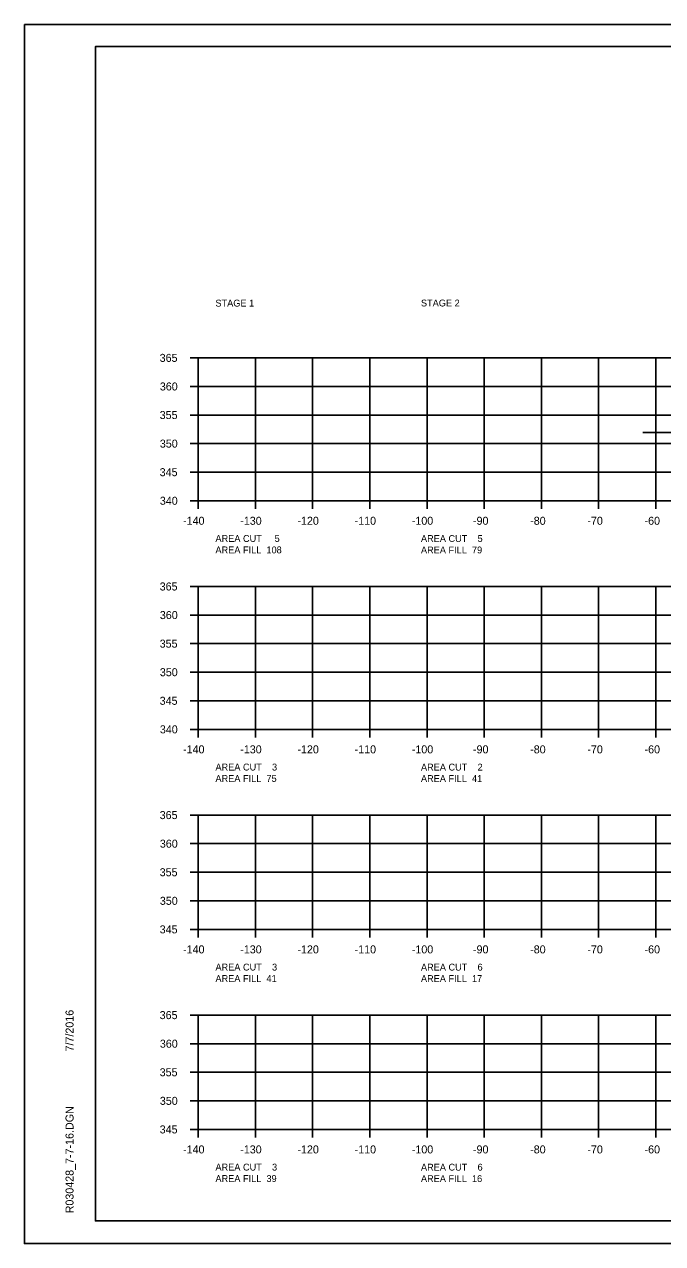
# Model space of a CAD drawing. Extents: x 1374859 to 1376773, y 382242 to 389804.
# Drawn here: x 1375964.2 to 1376075.8, y 382241.7 to 382455.1 of the extents above; entities that cross this region are included whole.
import ezdxf

# ---------------------------------------------------------------- set-up
doc = ezdxf.new("R2010")
doc.units = 0
for name, color, linetype in [('R_Axis', 7, 'Continuous'), ('R_Axis Annot', 7, 'Continuous'), ('R_Border', 7, 'Continuous'), ('R_Exist Surface', 7, 'Continuous'), ('R_Grid', 7, 'Continuous'), ('R_No Plot', 7, 'Continuous')]:
    doc.layers.add(name, color=color, linetype=linetype)

msp = doc.modelspace()

# ---------------------------------------------------------------- linework, layer by layer
at = {"layer": 'R_Axis'}
for p, q in [((1375993.17, 382396.72), (1375994.57, 382396.72)), ((1375994.57, 382371.72), (1375994.57, 382396.72)), ((1375993.17, 382391.72), (1375994.57, 382391.72)), ((1375993.17, 382386.72), (1375994.57, 382386.72)), ((1375993.17, 382381.72), (1375994.57, 382381.72)), ((1375993.17, 382376.72), (1375994.57, 382376.72)), ((1375993.17, 382371.72), (1375994.57, 382371.72)), ((1375994.57, 382371.72), (1376274.57, 382371.72)), ((1375994.57, 382370.32), (1375994.57, 382371.72)), ((1376004.57, 382370.32), (1376004.57, 382371.72)), ((1376014.57, 382370.32), (1376014.57, 382371.72)), ((1376024.57, 382370.32), (1376024.57, 382371.72)), ((1376034.57, 382370.32), (1376034.57, 382371.72)), ((1376044.57, 382370.32), (1376044.57, 382371.72)), ((1376054.57, 382370.32), (1376054.57, 382371.72)), ((1376064.57, 382370.32), (1376064.57, 382371.72)), ((1376074.57, 382370.32), (1376074.57, 382371.72)), ((1375993.17, 382356.72), (1375994.57, 382356.72)), ((1375994.57, 382331.72), (1375994.57, 382356.72)), ((1375993.17, 382351.72), (1375994.57, 382351.72)), ((1375993.17, 382346.72), (1375994.57, 382346.72)), ((1375993.17, 382341.72), (1375994.57, 382341.72)), ((1375993.17, 382336.72), (1375994.57, 382336.72)), ((1375993.17, 382331.72), (1375994.57, 382331.72)), ((1375994.57, 382331.72), (1376274.57, 382331.72)), ((1375994.57, 382330.32), (1375994.57, 382331.72)), ((1376004.57, 382330.32), (1376004.57, 382331.72)), ((1376014.57, 382330.32), (1376014.57, 382331.72)), ((1376024.57, 382330.32), (1376024.57, 382331.72)), ((1376034.57, 382330.32), (1376034.57, 382331.72)), ((1376044.57, 382330.32), (1376044.57, 382331.72)), ((1376054.57, 382330.32), (1376054.57, 382331.72)), ((1376064.57, 382330.32), (1376064.57, 382331.72)), ((1376074.57, 382330.32), (1376074.57, 382331.72)), ((1375993.17, 382316.72), (1375994.57, 382316.72)), ((1375994.57, 382296.72), (1375994.57, 382316.72)), ((1375993.17, 382311.72), (1375994.57, 382311.72)), ((1375993.17, 382306.72), (1375994.57, 382306.72)), ((1375993.17, 382301.72), (1375994.57, 382301.72)), ((1375993.17, 382296.72), (1375994.57, 382296.72)), ((1375994.57, 382296.72), (1376274.57, 382296.72)), ((1375994.57, 382295.32), (1375994.57, 382296.72)), ((1376004.57, 382295.32), (1376004.57, 382296.72)), ((1376014.57, 382295.32), (1376014.57, 382296.72)), ((1376024.57, 382295.32), (1376024.57, 382296.72)), ((1376034.57, 382295.32), (1376034.57, 382296.72)), ((1376044.57, 382295.32), (1376044.57, 382296.72)), ((1376054.57, 382295.32), (1376054.57, 382296.72)), ((1376064.57, 382295.32), (1376064.57, 382296.72)), ((1376074.57, 382295.32), (1376074.57, 382296.72)), ((1375993.17, 382281.72), (1375994.57, 382281.72)), ((1375994.57, 382261.72), (1375994.57, 382281.72)), ((1375993.17, 382276.72), (1375994.57, 382276.72)), ((1375993.17, 382271.72), (1375994.57, 382271.72)), ((1375993.17, 382266.72), (1375994.57, 382266.72)), ((1375993.17, 382261.72), (1375994.57, 382261.72)), ((1375994.57, 382261.72), (1376274.57, 382261.72)), ((1375994.57, 382260.32), (1375994.57, 382261.72)), ((1376004.57, 382260.32), (1376004.57, 382261.72)), ((1376014.57, 382260.32), (1376014.57, 382261.72)), ((1376024.57, 382260.32), (1376024.57, 382261.72)), ((1376034.57, 382260.32), (1376034.57, 382261.72)), ((1376044.57, 382260.32), (1376044.57, 382261.72)), ((1376054.57, 382260.32), (1376054.57, 382261.72)), ((1376064.57, 382260.32), (1376064.57, 382261.72)), ((1376074.57, 382260.32), (1376074.57, 382261.72))]:
    msp.add_line(p, q, dxfattribs=at)
at = {"layer": 'R_Border'}
for p, q in [((1375976.57, 382451.18), (1376292.75, 382451.18)), ((1375976.57, 382245.72), (1375976.57, 382451.18)), ((1375976.57, 382245.72), (1375976.57, 382245.72)), ((1376292.75, 382245.72), (1375976.57, 382245.72))]:
    msp.add_line(p, q, dxfattribs=at)
at = {"layer": 'R_Exist Surface'}
msp.add_lwpolyline([(1376072.31, 382383.65), (1376074.07, 382383.65), (1376082.2, 382383.68)], dxfattribs=at)
at = {"layer": 'R_Grid'}
for p, q in [((1375994.57, 382396.72), (1376274.57, 382396.72)), ((1375994.57, 382371.72), (1375994.57, 382396.72)), ((1376004.57, 382371.72), (1376004.57, 382396.72)), ((1376014.57, 382371.72), (1376014.57, 382396.72)), ((1376024.57, 382371.72), (1376024.57, 382396.72)), ((1376034.57, 382371.72), (1376034.57, 382396.72)), ((1376044.57, 382371.72), (1376044.57, 382396.72)), ((1376054.57, 382371.72), (1376054.57, 382396.72)), ((1376064.57, 382371.72), (1376064.57, 382396.72)), ((1376074.57, 382371.72), (1376074.57, 382396.72)), ((1375994.57, 382391.72), (1376274.57, 382391.72)), ((1375994.57, 382386.72), (1376274.57, 382386.72)), ((1375994.57, 382381.72), (1376274.57, 382381.72)), ((1375994.57, 382376.72), (1376274.57, 382376.72)), ((1375994.57, 382371.72), (1376274.57, 382371.72)), ((1375994.57, 382356.72), (1376274.57, 382356.72)), ((1375994.57, 382331.72), (1375994.57, 382356.72)), ((1376004.57, 382331.72), (1376004.57, 382356.72)), ((1376014.57, 382331.72), (1376014.57, 382356.72)), ((1376024.57, 382331.72), (1376024.57, 382356.72)), ((1376034.57, 382331.72), (1376034.57, 382356.72)), ((1376044.57, 382331.72), (1376044.57, 382356.72)), ((1376054.57, 382331.72), (1376054.57, 382356.72)), ((1376064.57, 382331.72), (1376064.57, 382356.72)), ((1376074.57, 382331.72), (1376074.57, 382356.72)), ((1375994.57, 382351.72), (1376274.57, 382351.72)), ((1375994.57, 382346.72), (1376274.57, 382346.72)), ((1375994.57, 382341.72), (1376274.57, 382341.72)), ((1375994.57, 382336.72), (1376274.57, 382336.72)), ((1375994.57, 382331.72), (1376274.57, 382331.72)), ((1375994.57, 382316.72), (1376274.57, 382316.72)), ((1375994.57, 382296.72), (1375994.57, 382316.72)), ((1376004.57, 382296.72), (1376004.57, 382316.72)), ((1376014.57, 382296.72), (1376014.57, 382316.72)), ((1376024.57, 382296.72), (1376024.57, 382316.72)), ((1376034.57, 382296.72), (1376034.57, 382316.72)), ((1376044.57, 382296.72), (1376044.57, 382316.72)), ((1376054.57, 382296.72), (1376054.57, 382316.72)), ((1376064.57, 382296.72), (1376064.57, 382316.72)), ((1376074.57, 382296.72), (1376074.57, 382316.72)), ((1375994.57, 382311.72), (1376274.57, 382311.72)), ((1375994.57, 382306.72), (1376274.57, 382306.72)), ((1375994.57, 382301.72), (1376274.57, 382301.72)), ((1375994.57, 382296.72), (1376274.57, 382296.72)), ((1375994.57, 382281.72), (1376274.57, 382281.72)), ((1375994.57, 382261.72), (1375994.57, 382281.72)), ((1376004.57, 382261.72), (1376004.57, 382281.72)), ((1376014.57, 382261.72), (1376014.57, 382281.72)), ((1376024.57, 382261.72), (1376024.57, 382281.72)), ((1376034.57, 382261.72), (1376034.57, 382281.72)), ((1376044.57, 382261.72), (1376044.57, 382281.72)), ((1376054.57, 382261.72), (1376054.57, 382281.72)), ((1376064.57, 382261.72), (1376064.57, 382281.72)), ((1376074.57, 382261.72), (1376074.57, 382281.72)), ((1375994.57, 382276.72), (1376274.57, 382276.72)), ((1375994.57, 382271.72), (1376274.57, 382271.72)), ((1375994.57, 382266.72), (1376274.57, 382266.72)), ((1375994.57, 382261.72), (1376274.57, 382261.72))]:
    msp.add_line(p, q, dxfattribs=at)
at = {"layer": 'R_No Plot'}
for p, q in [((1375964.17, 382455.07), (1376297.5, 382455.07)), ((1375964.17, 382241.74), (1376297.5, 382241.74))]:
    msp.add_line(p, q, dxfattribs=at)
for points in [[(1375964.16, 382455.07), (1376297.5, 382455.07), (1376297.5, 382241.74), (1375964.16, 382241.74)], [(1376210.49, 382451.18), (1376210.49, 382441.3), (1376246.22, 382441.3), (1376246.22, 382438.38), (1376269.42, 382438.38), (1376269.42, 382414.05), (1376292.75, 382414.05), (1376292.75, 382245.72), (1375976.57, 382245.72), (1375976.57, 382451.18)]]:
    msp.add_lwpolyline(points, close=True, dxfattribs=at)

# ---------------------------------------------------------------- texts
at = {"layer": 'R_Axis Annot'}
for s, p in [('STAGE 1', (1375997.57, 382405.7)), ('STAGE 2', (1376033.51, 382405.72))]:
    msp.add_text(s, height=1.2, rotation=360, dxfattribs=at).set_placement(p)
for s, height, p in [('365', 1.4, (1375987.82, 382396.02)), ('360', 1.4, (1375987.85, 382391.02)), ('355', 1.4, (1375987.82, 382386.02)), ('350', 1.4, (1375987.85, 382381.02)), ('345', 1.4, (1375987.82, 382376.02)), ('340', 1.4, (1375987.85, 382371.02)), ('-140', 1.4, (1375991.91, 382367.52)), ('-130', 1.4, (1376001.91, 382367.52)), ('-120', 1.4, (1376011.91, 382367.52)), ('-110', 1.4, (1376021.91, 382367.52)), ('-100', 1.4, (1376031.91, 382367.52)), ('-90', 1.4, (1376042.61, 382367.52)), ('-80', 1.4, (1376052.61, 382367.52)), ('-70', 1.4, (1376062.61, 382367.52)), ('-60', 1.4, (1376072.61, 382367.52)), ('AREA CUT     5', 1.2, (1375997.57, 382364.52)), ('AREA CUT    5', 1.2, (1376033.51, 382364.51)), ('AREA FILL  108', 1.2, (1375997.57, 382362.52)), ('AREA FILL  79', 1.2, (1376033.51, 382362.51)), ('365', 1.4, (1375987.82, 382356.02)), ('360', 1.4, (1375987.85, 382351.02)), ('355', 1.4, (1375987.82, 382346.02)), ('350', 1.4, (1375987.85, 382341.02)), ('345', 1.4, (1375987.82, 382336.02)), ('340', 1.4, (1375987.85, 382331.02)), ('-140', 1.4, (1375991.91, 382327.52)), ('-130', 1.4, (1376001.91, 382327.52)), ('-120', 1.4, (1376011.91, 382327.52)), ('-110', 1.4, (1376021.91, 382327.52)), ('-100', 1.4, (1376031.91, 382327.52)), ('-90', 1.4, (1376042.61, 382327.52)), ('-80', 1.4, (1376052.61, 382327.52)), ('-70', 1.4, (1376062.61, 382327.52)), ('-60', 1.4, (1376072.61, 382327.52)), ('AREA CUT    3', 1.2, (1375997.57, 382324.52)), ('AREA CUT    2', 1.2, (1376033.51, 382324.51)), ('AREA FILL  75', 1.2, (1375997.57, 382322.52)), ('AREA FILL  41', 1.2, (1376033.51, 382322.51)), ('365', 1.4, (1375987.82, 382316.02)), ('360', 1.4, (1375987.85, 382311.02)), ('355', 1.4, (1375987.82, 382306.02)), ('350', 1.4, (1375987.85, 382301.02)), ('345', 1.4, (1375987.82, 382296.02)), ('-140', 1.4, (1375991.91, 382292.52)), ('-130', 1.4, (1376001.91, 382292.52)), ('-120', 1.4, (1376011.91, 382292.52)), ('-110', 1.4, (1376021.91, 382292.52)), ('-100', 1.4, (1376031.91, 382292.52)), ('-90', 1.4, (1376042.61, 382292.52)), ('-80', 1.4, (1376052.61, 382292.52)), ('-70', 1.4, (1376062.61, 382292.52)), ('-60', 1.4, (1376072.61, 382292.52)), ('AREA CUT    3', 1.2, (1375997.57, 382289.52)), ('AREA CUT    6', 1.2, (1376033.51, 382289.51)), ('AREA FILL  41', 1.2, (1375997.57, 382287.52)), ('AREA FILL  17', 1.2, (1376033.51, 382287.51)), ('365', 1.4, (1375987.82, 382281.02)), ('360', 1.4, (1375987.85, 382276.02)), ('355', 1.4, (1375987.82, 382271.02)), ('350', 1.4, (1375987.85, 382266.02)), ('345', 1.4, (1375987.82, 382261.02)), ('-140', 1.4, (1375991.91, 382257.52)), ('-130', 1.4, (1376001.91, 382257.52)), ('-120', 1.4, (1376011.91, 382257.52)), ('-110', 1.4, (1376021.91, 382257.52)), ('-100', 1.4, (1376031.91, 382257.52)), ('-90', 1.4, (1376042.61, 382257.52)), ('-80', 1.4, (1376052.61, 382257.52)), ('-70', 1.4, (1376062.61, 382257.52)), ('-60', 1.4, (1376072.61, 382257.52)), ('AREA CUT    3', 1.2, (1375997.57, 382254.52)), ('AREA CUT    6', 1.2, (1376033.51, 382254.51)), ('AREA FILL  39', 1.2, (1375997.57, 382252.52)), ('AREA FILL  16', 1.2, (1376033.51, 382252.51))]:
    msp.add_text(s, height=height, dxfattribs=at).set_placement(p)
at = {"layer": 'R_Border'}
for s, p in [('7/7/2016', (1375972.76, 382275.36)), ('R030428_7-7-16.DGN', (1375972.76, 382247.04))]:
    msp.add_text(s, height=1.4, rotation=90, dxfattribs=at).set_placement(p)

doc.saveas('drawing.dxf')
